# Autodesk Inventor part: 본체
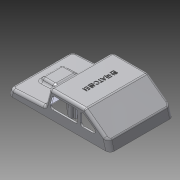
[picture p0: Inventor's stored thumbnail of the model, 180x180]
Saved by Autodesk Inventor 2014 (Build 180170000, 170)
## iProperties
Created: 2015-06
Part Number: 본체
Material: ABS 플라스틱
Document SubType Name: Modeling
Designer: Administrator
Density: 1.06 g/cm^3
Appearance: 매끄러움 - 흰색
Mass: 35.8865 g
Surface Area: 334.048 cm^2
Volume: 33.8551 cm^3
Author: Administrator
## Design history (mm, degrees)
sketch "스케치7"
  geometry: L1 (61, 0)-(-61, 0); L2 (61, 0)-(58.856, 8); L3 (58.856, 8)-(47.856, 8.576); L4 (47.856, 8.576)-(46.504, 13); L5 (46.504, 13)-(29.289, 13); L6 (27.856, 9.625)-(16.856, 10.201); L7 (16.856, 10.201)-(11.283, 31); L8 (11.283, 31)-(-31, 31); L9 (-31, 31)-(-58.053, 11); L10 (-58.053, 11)-(-61, 0); L11 (-61, 0)-(-61, 11); L12 (-61, 11)-(-58.053, 11); L13 (61, 0)-(61, 8); L14 (61, 8)-(58.856, 8); L15 (29.289, 13)-(27.856, 9.625); L16 (52.667, 0)-(52.667, -1); L17 (52.667, -1)-(-60, -1); L18 (-60, -1)-(-60, 0); 2 further points
  constraints: 36 end point, 7 perpendicular, 3 parallel, 2 collinear, 2 point on line, 1 coincident, 1 horizontal, 1 midpoint
  dimensions: "d12" = 122 distance of L1.start L1.end; "d13" = 31 vertical distance of L8.end L1.end; "d14" = 30 horizontal distance of L11.end L8.end; "d15" = 20 vertical distance of L9.end L8.end; "d16" = 8 vertical distance of L2.end L1.start; "d17" = 42 horizontal distance of L6.end L2.end; "d18" = 11 horizontal distance of L3.end L2.end; "d19" = 105 deg angle of L1 L2; "d20" = 105 deg angle of L1 L10; "d22" = 20 horizontal distance of L6.start L3.end; "d23" = 3 deg angle of L1 L6; "d24" = 70 deg angle of L3 L4; "d25" = 70 deg angle of L6 L15; "d26" = 5 vertical distance of L4.end L2.end; "d62" = 1 horizontal distance of L1.end L17.end; "d63" = 1 distance between parallel lines of L1 L17
extrude "돌출3" new body sketch "스케치7" stored distance "d27" = 76; taper "d28" = 0 deg
sketch "스케치8"
  geometry: L1 (-27.856, 9.625)-(-29.289, 13) reference; L2 (-29.289, 13)-(-46.504, 13) reference; L3 (-46.504, 13)-(-47.856, 8.576) reference; L4 (-47.856, 8.576)-(-58.856, 8) reference; L5 (-47.856, 8.576)-(-27.856, 9.625); 1 further point
  constraints: 2 end point, 1 collinear
extrude "돌출4" cut sketch "스케치8" distance "d29" = 25; taper "d30" = 0 deg
sketch "스케치9"
  geometry: L1 (-47.856, -8.576)-(-46.504, -13) reference; L2 (-46.504, -13)-(-29.289, -13) reference; L3 (-29.289, -13)-(-27.856, -9.625) reference; L4 (-27.856, -9.625)-(-16.856, -10.201) reference; L5 (-47.856, -8.576)-(-27.856, -9.625); 1 further point
  constraints: 2 end point, 1 collinear
extrude "돌출5" cut sketch "스케치9" distance "d31" = 25; taper "d32" = 0 deg
feature "쉘1" dims "d33" = 2
sketch "스케치10"
  geometry: L1 (31, 31)-(-11.283, 31) reference; L2 (-11.283, 31)-(-16.856, 10.201) reference; L3 (-5.145, 26)-(19.534, 26); L4 (22.534, 23)-(22.534, 14); L5 (19.534, 11)-(-7.556, 11); L6 (-10.454, 14.776)-(-8.043, 23.776); A1 r 3 centre (-5.145, 23) between (-5.145, 26) and (-8.043, 23.776); A2 r 3 centre (-7.556, 14) between (-10.454, 14.776) and (-7.556, 11); A3 r 3 centre (19.534, 14) between (19.534, 11) and (22.534, 14); A4 r 3 centre (19.534, 23) between (22.534, 23) and (19.534, 26); 3 further points
  constraints: 8 end point, 8 point on circle, 8 tangent, 4 centre point, 4 point on line, 3 equal radius, 3 parallel, 1 perpendicular
  dimensions: "d34" = 5 distance between parallel lines of L6 L2; "d35" = 34 distance of point (22.534, 11) point (-11.466, 11); "d36" = 5 distance between parallel lines of L1 L3; "d37" = 15 distance between parallel lines of L5 L3; "d38" = 3 radius of A1
extrude "돌출6" cut sketch "스케치10" stored distance "d39" = 25; taper "d40" = 0 deg
sketch "스케치11"
  geometry: L1 (58.053, 11)-(31, 31) reference; L2 (31, 31)-(-11.283, 31) reference; L3 (25.364, 23)-(25.364, 14); L4 (28.364, 11)-(40.538, 11); L5 (42.321, 16.412)-(30.147, 25.412); A1 r 3 centre (19.534, 23) between (22.534, 23) and (19.534, 26) reference; A2 r 3 centre (19.534, 14) between (19.534, 11) and (22.534, 14) reference; A3 r 3 centre (28.364, 23) between (30.147, 25.412) and (25.364, 23); A4 r 3 centre (28.364, 14) between (25.364, 14) and (28.364, 11); A5 r 3 centre (40.538, 14) between (40.538, 11) and (42.321, 16.412); 1 further point
  constraints: 6 end point, 6 point on circle, 6 tangent, 3 centre point, 2 horizontal alignment, 2 perpendicular, 1 parallel
  dimensions: "d41" = 5 distance between parallel lines of L1 L5; "d42" = 3 radius of A3; "d43" = 3 radius of A4; "d44" = 3 radius of A5
extrude "돌출7" cut sketch "스케치11" stored distance "d45" = 25; taper "d46" = 0 deg
sketch "스케치12"
  geometry: A1 r 4 centre (-8.282, 59) between (-8.282, 55) and (-8.282, 63); A2 r 4 centre (-8.282, 48) between (-8.282, 44) and (-8.282, 52); A3 r 4 centre (-8.282, 28) between (-8.282, 24) and (-8.282, 32); A4 r 4 centre (-8.282, 17) between (-8.282, 13) and (-8.282, 21); 3 further points
  constraints: 8 point on circle, 4 centre point, 13 other
  dimensions: "d47" = 8 diameter of A1; "d48" = 8 diameter of A2; "d49" = 8 diameter of A3; "d50" = 8 diameter of A4; "d51" = 10 vertical distance of A2.centre point (7.506, 38); "d52" = 10 vertical distance of A3.centre point (7.506, 38); "d53" = 11 distance of A4.centre A3.centre; "d54" = 11 distance of A1.centre A2.centre
extrude "돌출8" join sketch "스케치12" distance "d55" = 2; taper "d56" = 0 deg
fillet "모깎기3" dims "d57" = 3
fillet "모깎기4" dims "d58" = 3
sketch "스케치15"
  geometry: L1 (-61, -38)-(61, -38) reference; L2 (-61, -38)-(-61, -25) reference; L3 (-58.929, 36)-(-58.929, -36) reference; L4 (56.302, 36)-(56.302, -36) reference; L5 (58.929, 36)-(-58.929, 36) reference; L6 (-58.929, -36)-(58.929, -36) reference; C1 r 3 at (-40, 0); C2 r 3 at (0, 22); C3 r 3 at (40, 0); C4 r 3 at (0, -22); 2 further points
  constraints: 4 centre point, 2 horizontal alignment, 2 vertical alignment
  dimensions: "d65" = 6 diameter of C1; "d66" = 6 diameter of C2; "d67" = 6 diameter of C3; "d68" = 6 diameter of C4; "d69" = 40 distance of C1.centre point (0, 0); "d70" = 40 distance of C3.centre point (0, 0); "d71" = 22 distance of C2.centre point (0, 0); "d72" = 22 distance of C4.centre point (0, 0)
extrude "돌출9" join sketch "스케치15" stored distance "d73" = 2; taper "d74" = 0 deg
fillet "모깎기8" dims "d97" = 3
fillet "모깎기9" dims "d98" = 3
fillet "모깎기10" dims "d99" = 3
fillet "모깎기11" dims "d100" = 3
sketch "스케치32"
  geometry: L1 (5, -1)-(-5, -1); L2 (-5, -1)-(-5, 1); L3 (-5, 1)-(5, 1); L4 (5, 1)-(5, -1); L5 (5, -1)-(-5, 1); L6 (-5, -1)-(5, 1); C1 r 3 at (0, 0) reference; 1 further point
  constraints: 12 end point, 2 midpoint, 2 parallel, 1 horizontal, 1 perpendicular
  dimensions: "d124" = 10 distance of L2.end L3.end; "d125" = 2 distance of L1.end L2.end
extrude "돌출14" join sketch "스케치32" stored distance "d126" = 0; taper "d127" = 2.5 deg
sketch "스케치33"
  geometry: L1 (5, -1)-(-5, -1); L2 (-5, -1)-(-5, 1); L3 (-5, 1)-(5, 1); L4 (5, 1)-(5, -1); L5 (5, -1)-(-5, 1); L6 (-5, -1)-(5, 1); C1 r 3 at (0, 0) reference; 1 further point
  constraints: 12 end point, 2 midpoint, 2 parallel, 1 horizontal, 1 perpendicular
  dimensions: "d128" = 2 distance of L1.end L2.end; "d129" = 10 distance of L2.end L3.end
extrude "돌출15" join sketch "스케치33" stored distance "d130" = 0; taper "d131" = 2.5 deg
sketch "스케치34"
  geometry: L1 (5, -1)-(-5, -1); L2 (-5, -1)-(-5, 1); L3 (-5, 1)-(5, 1); L4 (5, 1)-(5, -1); L5 (5, -1)-(-5, 1); L6 (-5, -1)-(5, 1); C1 r 3 at (0, 0) reference; 1 further point
  constraints: 12 end point, 2 midpoint, 2 parallel, 1 horizontal, 1 perpendicular
  dimensions: "d132" = 2 distance of L1.end L2.end; "d133" = 10 distance of L2.end L3.end
extrude "돌출16" join sketch "스케치34" stored distance "d134" = 2; taper "d135" = 2.5 deg
sketch "스케치35"
  geometry: L1 (5, -1)-(-5, -1); L2 (-5, -1)-(-5, 1); L3 (-5, 1)-(5, 1); L4 (5, 1)-(5, -1); L5 (5, -1)-(-5, 1); L6 (-5, -1)-(5, 1); C1 r 3 at (0, 0) reference; 1 further point
  constraints: 12 end point, 2 midpoint, 2 parallel, 1 horizontal, 1 perpendicular
  dimensions: "d136" = 10 distance of L2.end L3.end; "d137" = 2 distance of L1.end L2.end
extrude "돌출17" join sketch "스케치35" stored distance "d138" = 0; taper "d139" = 2.5 deg
sketch "스케치36"
  geometry: L1 (-5, 23)-(-2.828, 23) reference; L2 (-5, 21)-(-5, 23) reference; L3 (-2.828, 21)-(-5, 21) reference; L4 (5, 21)-(2.828, 21) reference; L5 (5, 23)-(5, 21) reference; L6 (2.828, 23)-(5, 23) reference; L7 (-5, -21)-(-2.828, -21) reference; L8 (-5, -23)-(-5, -21) reference; L9 (-2.828, -23)-(-5, -23) reference; L10 (5, -23)-(2.828, -23) reference; L11 (5, -21)-(5, -23) reference; L12 (2.828, -21)-(5, -21) reference; L13 (-35, -1)-(-37.172, -1) reference; L14 (-35, 1)-(-35, -1) reference; L15 (-37.172, 1)-(-35, 1) reference; L16 (-45, 1)-(-42.828, 1) reference; L17 (-45, -1)-(-45, 1) reference; L18 (-42.828, -1)-(-45, -1) reference; A1 r 3 centre (40, 0) between (42.828, 1) and (37.172, 1) reference; A2 r 3 centre (0, 22) between (-2.828, 21) and (2.828, 21) reference; A3 r 3 centre (0, 22) between (2.828, 23) and (-2.828, 23) reference; A4 r 3 centre (0, -22) between (-2.828, -23) and (2.828, -23) reference; A5 r 3 centre (0, -22) between (2.828, -21) and (-2.828, -21) reference; A6 r 3 centre (-40, 0) between (-37.172, 1) and (-42.828, 1) reference; A7 r 3 centre (-40, 0) between (-42.828, -1) and (-37.172, -1) reference; 5 further points
  constraints: 4 coincident
hole "구멍3" sketch "스케치36" at (-40, 0), (0, 22), (0, -22), (40, 0) diameter "d140" = 3.242; stored, may be unused: countersink angle "d144" = 90 deg, drill point angle "d146" = 118 deg; dims "d141" = 9, "d142" = 4, "d143" = 2, "d145" = 11
fillet "모깎기12" dims "d147" = 5
sketch "스케치40"
  geometry: L1 (72.283, -5)-(72.283, -71) reference; 2 further points
  constraints: 1 horizontal alignment, 1 other
  dimensions: "d152" = 50 distance from line of point (22.283, -38) L1
feature "엠보싱3" sketch "스케치40" dims "d153" = 0.5, "d154" = 0
fillet "모깎기14" dims "d155" = 3
node "솔리드2"
node "투영된 루프7"
node "투영된 루프8"
node "투영된 루프9"
